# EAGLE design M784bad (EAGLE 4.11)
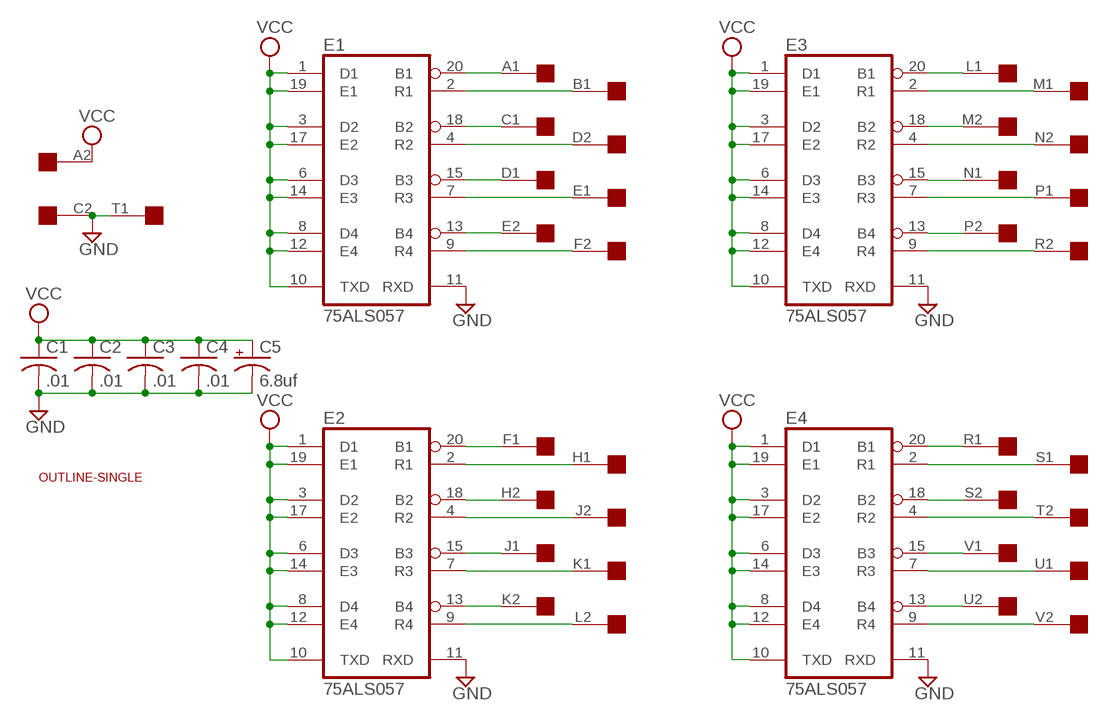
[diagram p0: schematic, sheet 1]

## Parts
C1  .01  C-US050-025X075  [C050-025X075]
C2  .01  C-US050-025X075  [C050-025X075]
C3  .01  C-US050-025X075  [C050-025X075]
C4  .01  C-US050-025X075  [C050-025X075]
C5  6.8uf  CPOL-USE15-5AXIAL  [E15-5]
E1  75ALS057  [DIL20]
E2  75ALS057  [DIL20]
E3  75ALS057  [DIL20]
E4  75ALS057  [DIL20]
U$1  SINGLE  [EDGE-CON2]
U$2  OUTLINE-SINGLE  [SINGLE]

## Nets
GND: C1.2 C2.2 C3.2 C4.2 C5.- E1.11(RXD) E2.11(RXD) E3.11(RXD) E4.11(RXD) U$1.C2 U$1.T1
N$1: E3.20(B1) U$1.L1
N$2: E3.2(R1) U$1.M1
N$3: E3.18(B2) U$1.M2
N$4: E3.4(R2) U$1.N2
N$5: E3.15(B3) U$1.N1
N$6: E3.7(R3) U$1.P1
N$7: E3.13(B4) U$1.P2
N$8: E3.9(R4) U$1.R2
N$9: E4.9(R4) U$1.V2
N$10: E4.13(B4) U$1.U2
N$11: E4.7(R3) U$1.U1
N$12: E4.15(B3) U$1.V1
N$13: E4.4(R2) U$1.T2
N$14: E4.18(B2) U$1.S2
N$15: E4.20(B1) U$1.R1
N$16: E4.2(R1) U$1.S1
N$17: E2.13(B4) U$1.K2
N$18: E2.9(R4) U$1.L2
N$19: E2.7(R3) U$1.K1
N$20: E2.15(B3) U$1.J1
N$21: E2.4(R2) U$1.J2
N$22: E2.18(B2) U$1.H2
N$23: E2.2(R1) U$1.H1
N$24: E2.20(B1) U$1.F1
N$25: E1.9(R4) U$1.F2
N$26: E1.13(B4) U$1.E2
N$27: E1.7(R3) U$1.E1
N$28: E1.15(B3) U$1.D1
N$29: E1.4(R2) U$1.D2
N$30: E1.18(B2) U$1.C1
N$31: E1.2(R1) U$1.B1
N$32: E1.20(B1) U$1.A1
VCC: C1.1 C2.1 C3.1 C4.1 C5.+ E1.1(D1) E1.3(D2) E1.6(D3) E1.8(D4) E1.10(TXD) E1.12(E4) E1.14(E3) E1.17(E2) E1.19(E1) E2.1(D1) E2.3(D2) E2.6(D3) E2.8(D4) E2.10(TXD) E2.12(E4) E2.14(E3) E2.17(E2) E2.19(E1) E3.1(D1) E3.3(D2) E3.6(D3) E3.8(D4) E3.10(TXD) E3.12(E4) E3.14(E3) E3.17(E2) E3.19(E1) E4.1(D1) E4.3(D2) E4.6(D3) E4.8(D4) E4.10(TXD) E4.12(E4) E4.14(E3) E4.17(E2) E4.19(E1) U$1.A2
Unconnected: U$1.B2

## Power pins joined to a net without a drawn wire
GND: E1.16(GND) E2.16(GND) E3.16(GND) E4.16(GND)
VCC: E1.5(VCC) E2.5(VCC) E3.5(VCC) E4.5(VCC)

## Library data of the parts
C1-C4 = rcl:C-US: CAPACITOR, American symbol
C5 = rcl:CPOL-US: POLARIZED CAPACITOR, American symbol
E1-E4 = dec-con:75ALS057: Qbus Compatible Transceiver
U$1 = dec-con:SINGLE: Single-Height DEC board
U$2 = dec-con:OUTLINE-*: Board outlines for DEC boards.

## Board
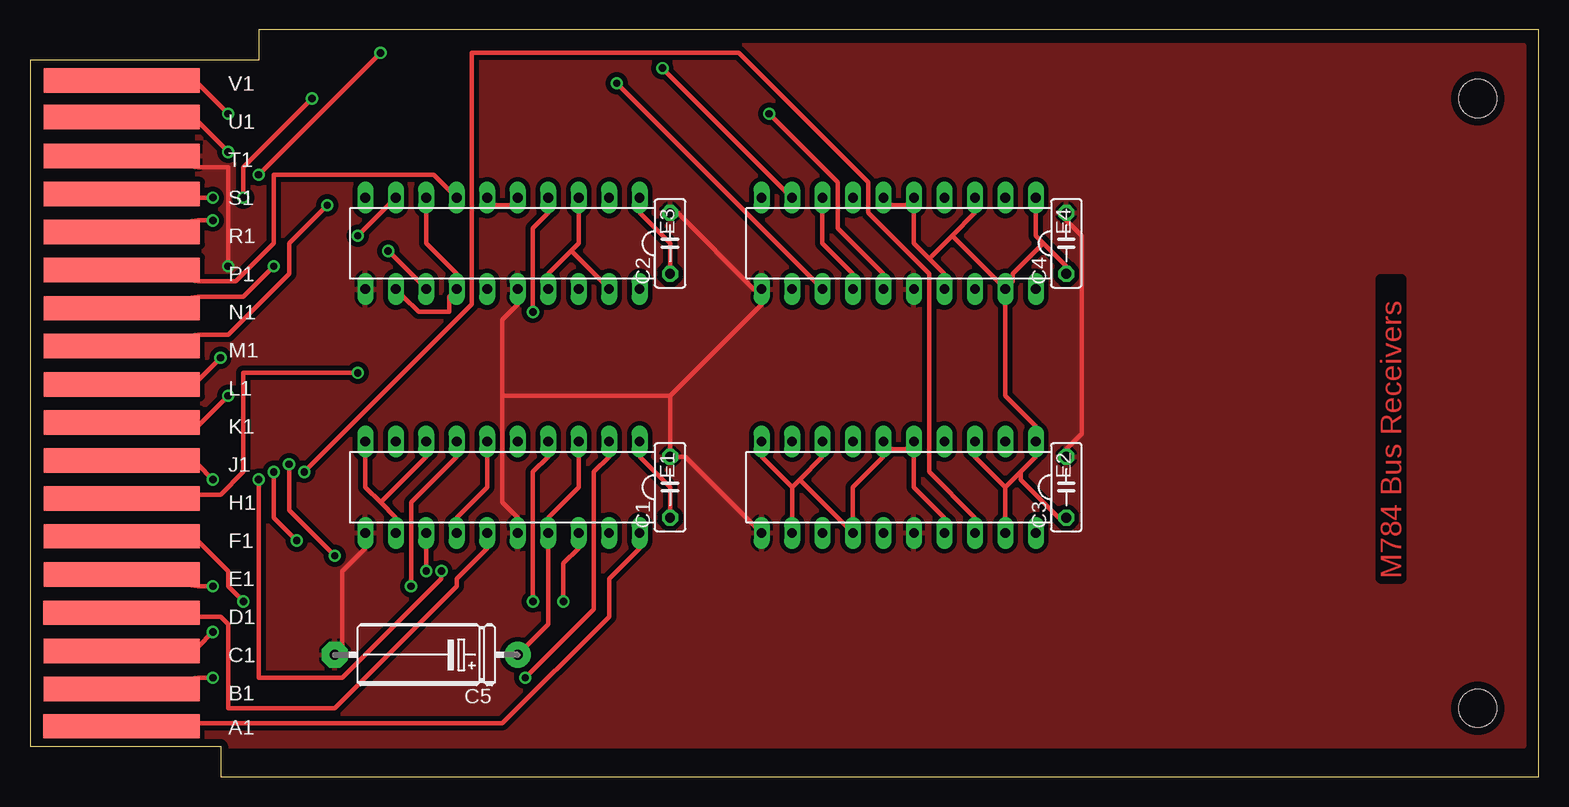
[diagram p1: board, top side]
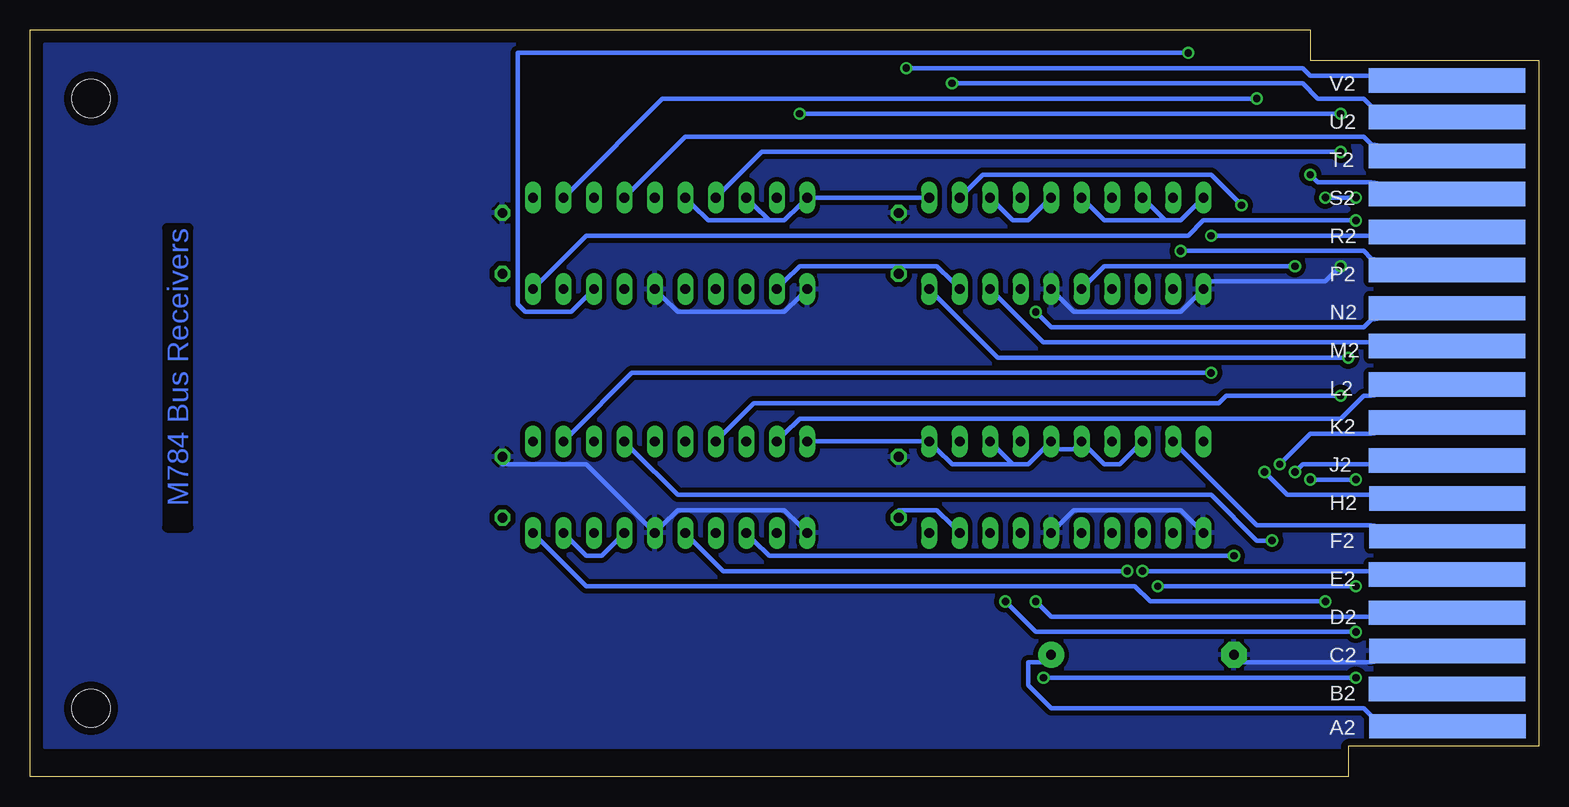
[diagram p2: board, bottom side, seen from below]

Size 125.73 x 62.23 mm. Coordinates in mm from the lower left corner, seen from the top.
Copper layers (1*16): Top 0.035mm / dielectric 1.5mm / Bottom 0.035mm
Design rules "15mils": minimum track width 15mil, minimum drill 24mil, track to track 15mil, track to pad 10mil, pad to pad 10mil, via to via 10mil, smd to smd 10mil, copper to edge 25mil, drill to drill 10mil, minimum pad ring 10mil, minimum via ring 8mil, stop-mask expansion 0mil, vias tented up to drill 0mil, thermal gap 10mil

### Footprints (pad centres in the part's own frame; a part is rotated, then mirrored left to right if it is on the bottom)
C050-025X075 = drill 0.813 octagon: 1 -2.54,0; 2 2.54,0
E15-5 = drill 0.813 pad 2.159 round: + -7.62,0 | drill 0.813 pad 2.159 octagon: - 7.62,0
DIL20 = drill 0.813 long: 1 -8.89,-3.81; 2 -6.35,-3.81; 3 -3.81,-3.81; 4 -1.27,-3.81; 5 1.27,-3.81; 6 3.81,-3.81; 7 6.35,-3.81; 8 8.89,-3.81; 9 11.43,-3.81; 10 13.97,-3.81; 11 13.97,3.81; 12 11.43,3.81; 13 8.89,3.81; 14 6.35,3.81; 15 3.81,3.81; 16 1.27,3.81; 17 -1.27,3.81; 18 -3.81,3.81; 19 -6.35,3.81; 20 -8.89,3.81
EDGE-CON2 = smd 13.017 x 2.032: A1 7.633,4.207; B1 7.639,7.327; C1 7.636,10.489; D1 7.633,13.665; E1 7.642,16.84; F1 7.642,20.041; H1 7.642,23.19; J1 7.642,26.34; K1 7.642,29.515; L1 7.642,32.69; M1 7.642,35.89; N1 7.642,39.04; P1 7.642,42.24; R1 7.642,45.39; S1 7.642,48.565; T1 7.642,51.74; U1 7.642,54.966; V1 7.642,58.026 | smd 13.017 x 2.032 bottom: A2 7.614,4.207; B2 7.642,7.328; C2 7.617,10.49; D2 7.642,13.665; E2 7.642,16.84; F2 7.617,20.041; H2 7.617,23.19; J2 7.642,26.34; K2 7.642,29.515; L2 7.642,32.69; M2 7.642,35.89; N2 7.642,39.04; P2 7.642,42.24; R2 7.642,45.39; S2 7.642,48.565; T2 7.642,51.74; U2 7.642,54.966; V2 7.642,58.026
SINGLE = hole 3.175: 120.65,56.515; 120.65,5.715

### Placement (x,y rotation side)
C1  53.34,24.13 90 top
C2  53.34,44.45 90 top
C3  86.36,24.13 90 top
C4  86.36,44.45 90 top
C5  33.02,10.16 180 top
E1  41.91,24.13 180 top
E2  74.93,24.13 180 top
E3  41.91,44.45 180 top
E4  74.93,44.45 180 top
U$1  0,0 0 top
U$2  0,0 0 top

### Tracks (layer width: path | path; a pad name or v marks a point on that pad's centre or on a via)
GND  (via drill 0.61)
  Top 0.381: C4.2 86.36,46.35 87.63,45.09 87.63,28.57 86.36,27.3 C3.2 | E2.11 60.33,20.95 54.61,26.67 53.98,26.67 C1.2 53.34,27.3 53.34,31.75 | 53.34,31.75 60.96,39.37 E4.11 60.33,40.64 53.98,46.99 C2.2 | E1.11 27.94,19.05 26.04,17.14 26.04,10.79 C5.- | 39.37,31.75 39.37,22.86 40.64,21.59 E1.16 | 39.37,31.75 39.37,38.1 40.64,39.37 E3.16 | v16.51,42.55 16.51,50.8 13.97,50.8 U$1.T1 | 39.37,31.75 53.34,31.75
  Bottom 0.381: C3.2 86.36,26.04 79.38,26.04 74.3,20.95 E2.16 73.03,20.95 71.76,22.23 62.87,22.23 61.6,20.95 E2.11 | E4.16 73.03,40.01 71.76,38.73 62.87,38.73 61.6,40.01 E4.11 | E3.16 40.01,40.01 38.74,38.73 29.85,38.73 28.58,40.01 E3.11 27.31,41.27 17.78,41.27 v16.51,42.55 | E1.16 40.01,20.95 38.74,22.23 29.85,22.23 28.58,20.95 E1.11 | U$1.C2 13.97,9.53 24.77,9.53 C5.-
  pour Bottom (isolate 0.406): 13.97,60.96 124.46,60.96 124.46,2.54 13.97,2.54
  pour Top (isolate 0.406): 13.97,60.96 124.46,60.96 124.46,2.54 13.97,2.54
N$1  (via drill 0.61)
  Top 0.381: v15.88,34.92 13.97,33.02 U$1.L1
  Bottom 0.381: v15.88,34.92 45.09,34.92 50.17,40.01 E3.20
N$2  (via drill 0.61)
  Top 0.381: v24.77,47.62 21.59,44.45 21.59,41.91 16.51,36.83 13.97,36.83 U$1.M1
  Bottom 0.381: v24.77,47.62 27.31,50.16 46.36,50.16 47.63,48.9 E3.2
N$3
  Bottom 0.381: E3.18 45.09,40.01 41.28,36.2 13.97,36.2 U$1.M2
N$4  (via drill 0.61)
  Top 0.381: v41.91,38.73 41.91,45.72 43.18,46.99 E3.4
  Bottom 0.381: v41.91,38.73 40.64,37.47 14.61,37.47 13.97,38.1 U$1.N2
N$5  (via drill 0.61)
  Top 0.381: v20.32,42.55 17.78,40.01 13.97,40.01 U$1.N1
  Bottom 0.381: v20.32,42.55 36.2,42.55 37.47,41.27 E3.15
N$6
  Top 0.381: E3.7 34.93,48.9 33.66,50.16 20.32,50.16 20.32,44.45 17.15,41.27 13.97,41.27 U$1.P1
N$7  (via drill 0.61)
  Top 0.381: v29.85,43.81 32.39,41.27 E3.13
  Bottom 0.381: v29.85,43.81 14.61,43.81 13.97,43.18 U$1.P2
N$8  (via drill 0.61)
  Top 0.381: v27.31,45.09 29.85,47.62 E3.9
  Bottom 0.381: v27.31,45.09 13.97,45.09 U$1.R2
N$9  (via drill 0.61)
  Top 0.381: v52.71,59.05 62.87,48.9 E4.9
  Bottom 0.381: v52.71,59.05 19.69,59.05 19.05,58.42 13.97,58.42 U$1.V2
N$10  (via drill 0.61)
  Top 0.381: v48.9,57.78 65.41,41.27 E4.13
  Bottom 0.381: v48.9,57.78 19.69,57.78 18.42,56.52 14.61,56.52 13.97,55.88 U$1.U2
N$11  (via drill 0.61)
  Top 0.381: v16.51,52.07 13.97,54.61 U$1.U1
  Bottom 0.381: v16.51,52.07 64.77,52.07 67.95,48.9 E4.7
N$12  (via drill 0.61)
  Top 0.381: v61.6,55.24 67.31,49.53 67.31,45.72 71.12,41.91 E4.15 | v16.51,55.24 13.97,57.78 U$1.V1
  Bottom 0.381: v16.51,55.24 v61.6,55.24
N$13
  Bottom 0.381: E4.4 75.57,48.9 71.12,53.34 14.61,53.34 13.97,52.7 U$1.T2
N$14  (via drill 0.61)
  Top 0.381: v19.05,50.16 v29.21,60.33
  Bottom 0.381: v29.21,60.33 85.09,60.33 85.09,39.37 84.46,38.73 80.65,38.73 79.38,40.01 E4.18 | v19.05,50.16 18.42,49.53 13.97,49.53 U$1.S2
N$15  (via drill 0.61)
  Top 0.381: v15.24,46.35 13.97,46.35 U$1.R1
  Bottom 0.381: v15.24,46.35 27.94,46.35 29.21,45.09 79.38,45.09 83.19,41.27 E4.20
N$16  (via drill 0.61)
  Top 0.381: v23.5,56.52 17.78,50.8 v17.78,48.26 | v15.24,48.26 13.97,48.26 U$1.S1
  Bottom 0.381: v23.5,56.52 73.03,56.52 80.65,48.9 E4.2 | v15.24,48.26 v17.78,48.26
N$17  (via drill 0.61)
  Top 0.381: v25.4,18.41 21.59,22.23 v21.59,26.04
  Bottom 0.381: v25.4,18.41 64.14,18.41 65.41,19.68 E2.13 | v21.59,26.04 19.05,28.57 13.97,28.57 U$1.K2
N$18
  Bottom 0.381: E2.9 62.87,28.57 61.6,29.84 16.51,29.84 14.61,31.75 13.97,31.75 U$1.L2
N$19  (via drill 0.61)
  Top 0.381: v16.51,31.75 13.97,29.21 U$1.K1
  Bottom 0.381: v16.51,31.75 26.04,31.75 26.67,31.11 65.41,31.11 67.95,28.57 E2.7
N$20  (via drill 0.61)
  Top 0.381: v34.29,17.14 34.29,16.51 26.04,8.26 19.05,8.26 v19.05,24.77 | v15.24,24.77 13.97,26.04 U$1.J1
  Bottom 0.381: v34.29,17.14 67.95,17.14 70.49,19.68 E2.15 | v19.05,24.77 v15.24,24.77
N$21  (via drill 0.61)
  Top 0.381: v22.23,19.68 20.32,21.59 v20.32,25.4
  Bottom 0.381: v22.23,19.68 23.5,19.68 27.31,23.5 71.76,23.5 75.57,27.3 E2.4 | v20.32,25.4 19.69,26.04 13.97,26.04 U$1.J2
N$22  (via drill 0.61)
  Top 0.381: v22.86,25.4 36.83,39.37 36.83,60.33 59.06,60.33 69.85,49.53 69.85,46.99 74.93,41.91 74.93,25.4 78.74,21.59 E2.18
  Bottom 0.381: v22.86,25.4 20.96,23.5 13.97,23.5 U$1.H2
N$23  (via drill 0.61)
  Top 0.381: v27.31,33.66 17.78,33.66 17.78,25.4 15.88,23.5 13.97,23.5 U$1.H1
  Bottom 0.381: v27.31,33.66 75.57,33.66 80.65,28.57 E2.2
N$24  (via drill 0.61)
  Top 0.381: v17.78,14.61 16.51,15.88 16.51,17.14 13.97,19.68 U$1.F1
  Bottom 0.381: v17.78,14.61 32.39,14.61 33.66,15.88 79.38,15.88 83.19,19.68 E2.20
N$25
  Bottom 0.381: E1.9 29.85,27.3 23.5,20.95 13.97,20.95 U$1.F2
N$26  (via drill 0.61)
  Top 0.381: v33.02,17.14 33.02,19.05 E1.13
  Bottom 0.381: v33.02,17.14 13.97,17.14 U$1.E2
N$27  (via drill 0.61)
  Top 0.381: v31.75,15.88 31.75,22.86 35.56,26.67 E1.7 | v15.24,15.88 13.97,15.88 U$1.E1
  Bottom 0.381: v15.24,15.88 v31.75,15.88
N$28
  Top 0.381: E1.15 38.1,19.05 35.56,16.51 35.56,15.88 25.4,5.71 16.51,5.71 16.51,12.7 15.88,13.34 13.97,13.34 U$1.D1
N$29  (via drill 0.61)
  Top 0.381: v41.91,14.61 41.91,25.4 43.18,26.67 E1.4
  Bottom 0.381: v41.91,14.61 40.64,13.34 13.97,13.34 U$1.D2
N$30  (via drill 0.61)
  Top 0.381: v44.45,14.61 44.45,17.78 45.72,19.05 E1.18 | v15.24,12.06 13.97,10.79 U$1.C1
  Bottom 0.381: v44.45,14.61 41.91,12.06 v15.24,12.06
N$31  (via drill 0.61)
  Top 0.381: v41.28,8.26 46.99,13.97 46.99,25.4 48.26,26.67 E1.2 | v15.24,8.26 13.97,8.26 U$1.B1
  Bottom 0.381: v15.24,8.26 v41.28,8.26
N$32
  Top 0.381: E1.20 50.8,19.05 48.26,16.51 48.26,13.34 39.37,4.45 13.97,4.45 U$1.A1
VCC
  Top 0.381: 81.28,24.13 78.74,26.67 E2.3 | 81.28,24.13 81.28,21.59 E2.19 | 81.28,24.13 82.55,25.4 | 82.55,25.4 83.82,26.67 E2.1 83.82,29.21 81.28,31.75 81.28,39.37 E4.19 | 82.55,25.4 82.55,24.77 85.73,21.59 C3.1 | 84.46,44.45 83.82,45.09 83.82,46.99 E4.1 | 84.46,44.45 86.36,42.55 C4.1 | E4.6 71.76,47.62 73.03,47.62 E4.5 73.66,46.99 73.66,44.45 74.93,43.18 | 74.93,43.18 76.2,41.91 E4.17 | 76.84,45.09 74.93,43.18 | 76.84,45.09 78.74,46.99 E4.3 | 76.84,45.09 80.65,41.27 E4.19 | 84.46,44.45 81.92,41.91 81.92,41.27 E4.19 | E3.12 31.12,40.01 32.39,38.73 34.93,38.73 34.93,40.01 E3.14 35.56,41.91 33.02,44.45 33.02,46.99 E3.8 | E3.6 38.74,47.62 40.01,47.62 E3.5 | 45.09,43.81 45.72,44.45 45.72,46.99 E3.3 | 45.09,43.81 43.18,41.91 E3.17 | 45.09,43.81 47.63,41.27 E3.19 | E3.1 50.8,46.99 53.34,44.45 53.34,42.55 C2.1 | E4.14 68.58,41.91 66.04,44.45 66.04,46.99 E4.8 | E2.17 76.2,21.59 73.66,24.13 73.66,26.67 E2.5 73.03,27.3 71.76,27.3 E2.6 71.12,26.67 68.58,24.13 68.58,21.59 E2.14 67.95,20.95 64.14,24.77 | E1.1 50.8,26.67 53.34,24.13 53.34,22.23 C1.1 | 63.5,24.13 60.96,26.67 E2.10 | 63.5,24.13 63.5,21.59 E2.12 | 63.5,24.13 64.14,24.77 | 64.14,24.77 66.04,26.67 E2.8 | 29.21,22.86 27.94,24.13 27.94,26.67 E1.10 | 29.21,22.86 30.48,21.59 E1.12 | 29.21,22.86 33.02,26.67 E1.8 | E1.14 35.56,21.59 38.1,24.13 38.1,26.67 E1.6 | E1.3 45.72,26.67 45.72,24.13 43.18,21.59 E1.17 43.18,19.05 43.18,12.7 41.28,10.79 C5.+
  Bottom 0.381: 31.12,46.35 29.85,46.35 28.58,47.62 E3.10 | 31.12,46.35 32.39,47.62 E3.8 | 31.12,46.35 36.2,46.35 37.47,47.62 E3.6 | E3.1 51.44,48.26 60.33,48.26 E4.10 61.6,47.62 62.87,46.35 64.14,46.35 | 53.34,42.55 61.6,42.55 62.87,41.27 E4.12 | 53.34,42.55 C2.1 53.34,42.55 | 64.14,46.35 65.41,47.62 E4.8 | 53.34,42.55 50.17,42.55 48.9,41.27 E3.19 | E3.5 41.28,47.62 42.55,46.35 43.82,46.35 45.09,47.62 E3.3 | 64.14,46.35 69.22,46.35 70.49,47.62 E4.6 | E1.19 48.9,20.95 50.17,22.23 53.34,22.23 C1.1 | E2.10 60.33,27.94 51.44,27.94 E1.1 50.17,27.3 48.9,26.04 43.82,26.04 | E1.8 33.66,27.3 34.93,26.04 36.2,26.04 37.47,27.3 E1.6 38.74,27.3 40.01,27.3 E1.5 41.28,27.3 42.55,26.04 43.82,26.04 | 43.82,26.04 45.09,27.3 E1.3 | U$1.A2 13.97,5.08 14.61,5.71 40.64,5.71 42.55,7.62 42.55,9.53 41.28,9.53 C5.+ | E2.19 80.65,19.68 79.38,18.41 78.11,18.41 76.84,19.68 E2.17

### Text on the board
Top: M784 Bus Receivers
Bottom: M784 Bus Receivers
